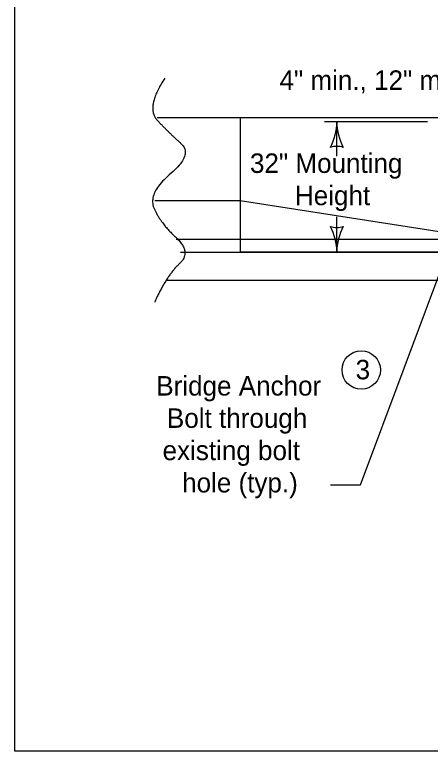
# Model space of a CAD drawing. Extents: x 10028 to 81668, y 3581 to 11018.
# Drawn here: x 17333 to 17657, y 7924 to 8499 of the extents above; entities that cross this region are included whole.
import ezdxf

# ---------------------------------------------------------------- set-up
doc = ezdxf.new("R2010")
doc.units = 0
for name, color, linetype in [('dsnCellsNorthArrow', 7, 'Continuous'), ('dsnTextTabulation', 7, 'Continuous'), ('Level 9', 7, 'Continuous'), ('SheetBorder', 7, 'Continuous')]:
    doc.layers.add(name, color=color, linetype=linetype)

msp = doc.modelspace()

# ---------------------------------------------------------------- linework, layer by layer
at = {"layer": 'dsnCellsNorthArrow'}
msp.add_line((17757.55, 8313.61), (17508.52, 8313.61), dxfattribs=at)
at = {"layer": 'dsnTextTabulation'}
for p, q in [((17508.52, 8418.46), (17443.81, 8418.46)), ((17508.52, 8418.46), (17508.52, 8313.61)), ((17757.59, 8418.46), (17508.52, 8418.46)), ((17654.8, 8415.38), (17574.52, 8415.38)), ((17584.09, 8388.43), (17584.09, 8415.38)), ((17602.63, 8132.06), (17690.3, 8366.86)), ((17508.52, 8353.62), (17441.93, 8353.62)), ((17703.15, 8323.37), (17508.52, 8353.62)), ((17584.09, 8313.61), (17584.09, 8341.06)), ((17703.15, 8323.37), (17508.52, 8323.37)), ((17579.03, 8132.06), (17602.63, 8132.06))]:
    msp.add_line(p, q, dxfattribs=at)
msp.add_circle((17603.13, 8221.63), 15, dxfattribs=at)
for centre, radius, start, end in [((17541.59, 8415.38), 42.5, 331.92751, 360), ((17626.59, 8415.38), 42.5, 180, 208.07249), ((17584.09, 8379.74), 16.42, 72.26665, 107.73335), ((17584.09, 8349.24), 16.42, 252.26665, 287.73335), ((17541.59, 8313.61), 42.5, 360, 28.07249), ((17626.59, 8313.61), 42.5, 151.92751, 180)]:
    msp.add_arc(centre, radius, start, end, dxfattribs=at)
at = {"layer": 'Level 9'}
for p, q in [((17508.52, 8323.37), (17458.71, 8323.37)), ((17461.95, 8313.61), (20253.11, 8313.61)), ((17450.88, 8291.66), (17757.59, 8291.66))]:
    msp.add_line(p, q, dxfattribs=at)
msp.add_open_spline([(17449.63, 8449.28), (17434.55, 8426.2), (17453.18, 8406.67), (17471.82, 8389.8), (17436.32, 8359.61), (17446.08, 8336.52), (17470.93, 8313.44), (17451.41, 8295.68), (17441.65, 8274.37)], degree=2, dxfattribs=at)
at = {"layer": 'SheetBorder'}
msp.add_lwpolyline([(17332.52, 9944.02), (20467.53, 9944.02), (20467.53, 7924.02), (17332.52, 7924.02)], close=True, dxfattribs=at)

# ---------------------------------------------------------------- texts
at = {"layer": 'dsnCellsNorthArrow'}
for s, p in [('4" min., 12" max.', (17539.28, 8440.26)), ('32" Mounting', (17516.24, 8375.43)), ('Height', (17551.35, 8350.23)), ('Bridge Anchor', (17443.06, 8201.65)), ('Bolt through', (17451.38, 8176.45)), ('existing bolt ', (17447.98, 8151.25)), ('hole (typ.)', (17463.24, 8126.05))]:
    msp.add_text(s, height=15.2, dxfattribs=at).set_placement(p)
at = {"layer": 'dsnTextTabulation'}
msp.add_text('3', height=15.2, dxfattribs=at).set_placement((17598.76, 8214.34))

doc.saveas('drawing.dxf')
